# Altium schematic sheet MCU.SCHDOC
size B; Organization: Altium Limited; Address1: L3, 12a Rodborough Rd; Address2: Frenchs Forest; Address3: NSW; Address4: Australia 2086; DocumentNumber: 1; SheetNumber: 1; SheetTotal: 1
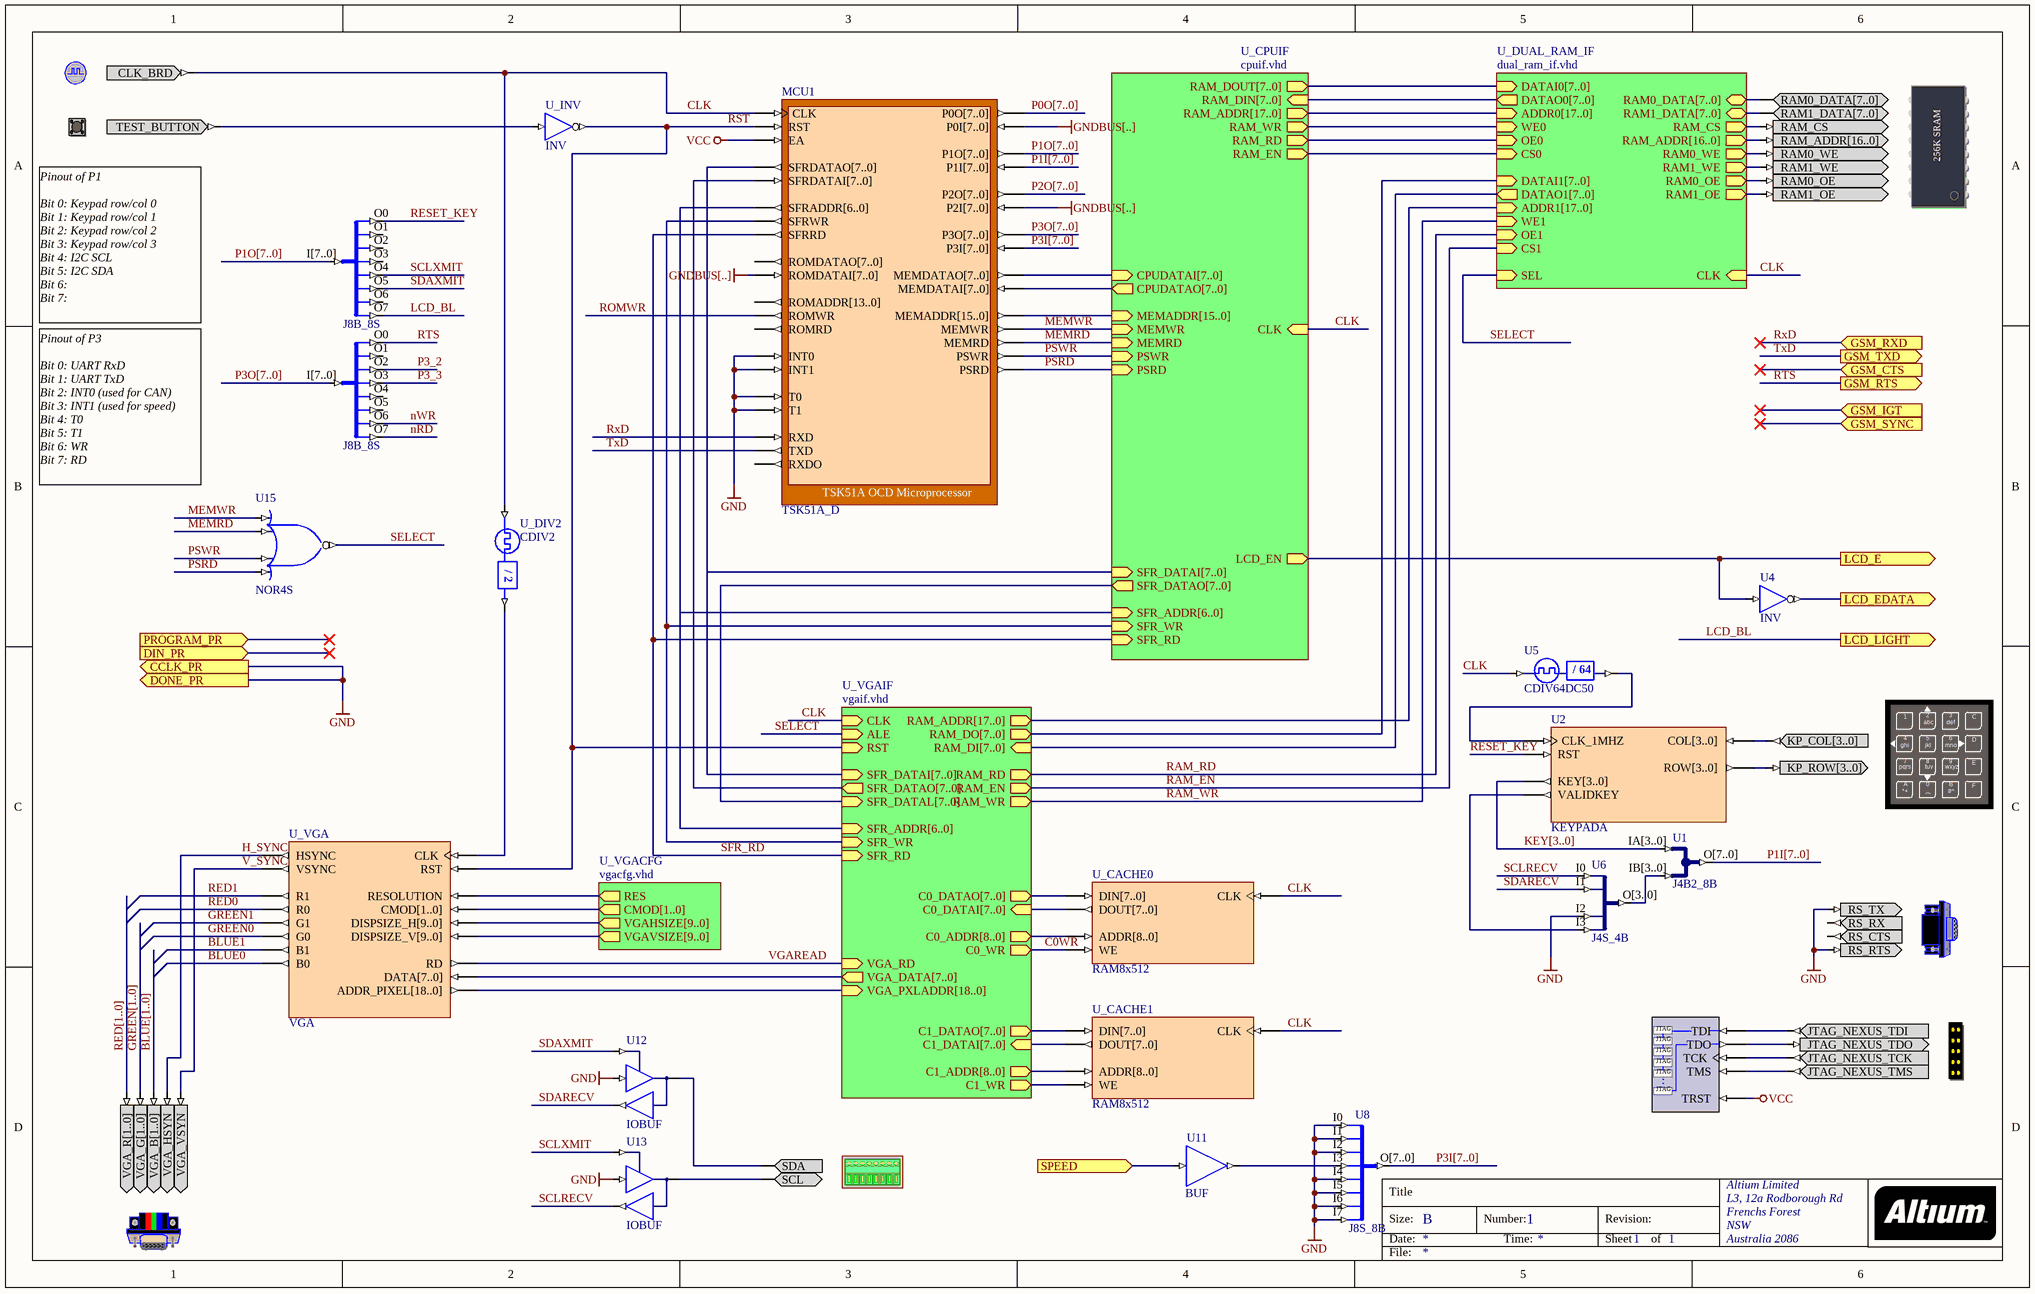
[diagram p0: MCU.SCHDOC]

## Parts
(Parts that share a designator on the sheet are numbered #1, #2 ... from top to bottom, then left to right.)
?#1  KEYPAD  (value not drawn)
?#2  RS232CNTR  (value not drawn)
?#3  NEXUS_JTAG_CONNECTOR  (value not drawn)
?#4  ADCDAC_I2C  (value not drawn)
MCU1  TSK51A_D
NEXUS_JTAG_PORT  NEXUS_JTAG_PORT  (value not drawn)
SRAM256kx8B  MEMORY256KX8  (value not drawn)
U1  J4B2_8B
U2  KEYPADA
U4  INV
U5  CDIV64DC50
U6  J4S_4B
U7  J8B_8S
U8  J8S_8B
U11  BUF
U12  IOBUF
U13  IOBUF
U15  NOR4S
U18  J8B_8S
U_CACHE0  RAM8x512
U_CACHE1  RAM8x512
U_CLKEXT  CLOCK_BOARD  (value not drawn)
U_DIV2  CDIV2
U_INV  INV
U_RSTEXT  TEST_BUTTON  (value not drawn)
U_VGA  VGA
U_VGAEXT  VGACNTR  (value not drawn)

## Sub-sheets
U_CPUIF = cpuif.vhd: MEMWR (in), RAM_EN (out), RAM_WR (out), RAM_RD (out), RAM_DOUT[7..0] (out), MEMRD (in), LCD_EN (out), RAM_ADDR[17..0] (out), CLK (in), SFR_ADDR[6..0] (in), SFR_DATAI[7..0] (in), SFR_DATAO[7..0] (out), SFR_WR (in), SFR_RD (in), RAM_DIN[7..0] (in), PSWR (in), PSRD (in), MEMADDR[15..0] (in), CPUDATAI[7..0] (in), CPUDATAO[7..0] (out)
U_DUAL_RAM_IF = dual_ram_if.vhd: DATAI0[7..0] (in), DATAI1[7..0] (in), DATAO0[7..0] (out), DATAO1[7..0] (out), ADDR0[17..0] (in), ADDR1[17..0] (in), WE0 (in), WE1 (in), OE0 (in), OE1 (in), CS0 (in), CS1 (in), SEL (in), RAM0_DATA[7..0] (bidir), RAM1_DATA[7..0] (bidir), RAM_ADDR[16..0] (out), RAM0_WE (out), RAM1_WE (out), RAM0_OE (out), RAM1_OE (out), RAM_CS (out), CLK (in)
U_VGACFG = vgacfg.vhd: RES (out), CMOD[1..0] (out), VGAHSIZE[9..0] (out), VGAVSIZE[9..0] (out)
U_VGAIF = vgaif.vhd: VGA_PXLADDR[18..0] (in), VGA_DATA[7..0] (out), VGA_RD (in), C1_WR (out), C1_ADDR[8..0] (out), C1_DATAI[7..0] (in), C1_DATAO[7..0] (out), C0_WR (out), C0_ADDR[8..0] (out), C0_DATAI[7..0] (in), C0_DATAO[7..0] (out), RAM_ADDR[17..0] (out), CLK (in), ALE (in), RAM_DO[7..0] (out), RAM_RD (out), RAM_EN (out), RAM_WR (out), SFR_ADDR[6..0] (in), SFR_DATAI[7..0] (in), SFR_DATAO[7..0] (out), SFR_WR (in), SFR_RD (in), SFR_DATAL[7..0] (in), RAM_DI[7..0] (in), RST (in)

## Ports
CCLK_PR (out), DIN_PR (in), DONE_PR (out), GSM_CTS (in), GSM_IGT (in), GSM_RTS (out), GSM_RXD (in), GSM_SYNC (in), GSM_TXD (out), LCD_E (out), LCD_EDATA (out), LCD_LIGHT (out), PROGRAM_PR (in), SPEED (in)

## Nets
GND: ?#2.RS_RTS ?#2.RS_TX MCU1.INT0 MCU1.INT1 MCU1.T0 MCU1.T1 U6.I2 U8.I0 U8.I1 U8.I2 U8.I4 U8.I5 U8.I6 U8.I7 U12.I U13.I ; port CCLK_PR, port DONE_PR
VCC: MCU1.EA NEXUS_JTAG_PORT.TRST
BLUE0: U_VGA.B0
BLUE1: U_VGA.B1
C0WR: U_CACHE0.WE ; sheet U_VGAIF/C0_WR
CLK: MCU1.CLK U5.CLKIN U_CACHE0.CLK U_CACHE1.CLK U_CLKEXT.CLK_BRD U_DIV2.CLKIN ; sheet U_CPUIF/CLK, sheet U_VGAIF/CLK, sheet U_DUAL_RAM_IF/CLK
GREEN0: U_VGA.G0
GREEN1: U_VGA.G1
H_SYNC: U_VGA.HSYNC U_VGAEXT.VGA_HSYN
LCD_BL: U18.O7 ; port LCD_LIGHT
LCD_E: U4.I ; port LCD_E, sheet U_CPUIF/LCD_EN
LCD_EDATA: U4.O ; port LCD_EDATA
MEMRD: MCU1.MEMRD U15.I1 ; sheet U_CPUIF/MEMRD
MEMWR: MCU1.MEMWR U15.I0 ; sheet U_CPUIF/MEMWR
nRD: U7.O7
nWR: U7.O6
P3_2: U7.O2
P3_3: U7.O3
PSRD: MCU1.PSRD U15.I3 ; sheet U_CPUIF/PSRD
PSWR: MCU1.PSWR U15.I2 ; sheet U_CPUIF/PSWR
RAM_EN: sheet U_VGAIF/RAM_EN, sheet U_DUAL_RAM_IF/CS1
RAM_RD: sheet U_VGAIF/RAM_RD, sheet U_DUAL_RAM_IF/OE1
RAM_WR: sheet U_VGAIF/RAM_WR, sheet U_DUAL_RAM_IF/WE1
RED0: U_VGA.R0
RED1: U_VGA.R1
RESET_KEY: U2.RST U18.O0
ROMWR: MCU1.ROMWR
RST: MCU1.RST U_INV.O U_VGA.RST ; sheet U_VGAIF/RST
RTS: U7.O0 ; port GSM_RTS
RxD: MCU1.RXD ; port GSM_RXD
SCLRECV: U6.I0 U13.O
SCLXMIT: U13.T U18.O4
SDARECV: U6.I1 U12.O
SDAXMIT: U12.T U18.O5
SELECT: U15.O ; sheet U_VGAIF/ALE, sheet U_DUAL_RAM_IF/SEL
SFR_RD: MCU1.SFRRD ; sheet U_CPUIF/SFR_RD, sheet U_VGAIF/SFR_RD
SPEED: U11.I ; port SPEED
TxD: MCU1.TXD ; port GSM_TXD
V_SYNC: U_VGA.VSYNC U_VGAEXT.VGA_VSYN
VGAREAD: U_VGA.RD ; sheet U_VGAIF/VGA_RD
Net?#3_JTAG_NEXUS_TCK: ?#3.JTAG_NEXUS_TCK NEXUS_JTAG_PORT.TCK
Net?#3_JTAG_NEXUS_TDI: ?#3.JTAG_NEXUS_TDI NEXUS_JTAG_PORT.TDI
Net?#3_JTAG_NEXUS_TDO: ?#3.JTAG_NEXUS_TDO NEXUS_JTAG_PORT.TDO
Net?#3_JTAG_NEXUS_TMS: ?#3.JTAG_NEXUS_TMS NEXUS_JTAG_PORT.TMS
Net?#4_SCL: ?#4.SCL U13.IO
Net?#4_SDA: ?#4.SDA U12.IO
NetMCU1_SFRWR: MCU1.SFRWR ; sheet U_CPUIF/SFR_WR, sheet U_VGAIF/SFR_WR
NetSRAM256kx8B_RAM0_OE: SRAM256kx8B.RAM0_OE ; sheet U_DUAL_RAM_IF/RAM0_OE
NetSRAM256kx8B_RAM0_WE: SRAM256kx8B.RAM0_WE ; sheet U_DUAL_RAM_IF/RAM0_WE
NetSRAM256kx8B_RAM1_OE: SRAM256kx8B.RAM1_OE ; sheet U_DUAL_RAM_IF/RAM1_OE
NetSRAM256kx8B_RAM1_WE: SRAM256kx8B.RAM1_WE ; sheet U_DUAL_RAM_IF/RAM1_WE
NetSRAM256kx8B_RAM_CS: SRAM256kx8B.RAM_CS ; sheet U_DUAL_RAM_IF/RAM_CS
NetU2_CLK_1MHZ: U2.CLK_1MHZ U5.CLKDV
NetU2_VALIDKEY: U2.VALIDKEY U6.I3
NetU8_I3: U8.I3 U11.O
NetU_CACHE1_WE: U_CACHE1.WE ; sheet U_VGAIF/C1_WR
NetU_DIV2_CLKDV: U_DIV2.CLKDV U_VGA.CLK
NetU_INV_I: U_INV.I U_RSTEXT.TEST_BUTTON
NetU_VGA_RESOLUTION: U_VGA.RESOLUTION ; sheet U_VGACFG/RES
(unnamed): sheet U_CPUIF/RAM_EN, sheet U_DUAL_RAM_IF/CS0
(unnamed): sheet U_CPUIF/RAM_WR, sheet U_DUAL_RAM_IF/WE0  [a separate net that carries the same name]
(unnamed): sheet U_CPUIF/RAM_RD, sheet U_DUAL_RAM_IF/OE0  [a separate net that carries the same name]

Not connected (* = marked no-connect by the designer): ?#1 KP_COL[3..0] KP_ROW[3..0]; ?#2 RS_CTS RS_RX; MCU1 MEMADDR[15..0] MEMDATAI[7..0] MEMDATAO[7..0] P0I[7..0] P0O[7..0] P1I[7..0] P1O[7..0] P2I[7..0] P2O[7..0] P3I[7..0] P3O[7..0] ROMADDR[13..0] ROMDATAI[7..0] ROMDATAO[7..0] ROMRD RXDO SFRADDR[6..0] SFRDATAI[7..0] SFRDATAO[7..0]; SRAM256kx8B RAM0_DATA[7..0] RAM1_DATA[7..0] RAM_ADDR[16..0]; U1 IA[3..0] IB[3..0] O[7..0]; U2 COL[3..0] KEY[3..0] ROW[3..0]; U6 O[3..0]; U7 I[7..0] O1 O4 O5; U8 O[7..0]; U18 I[7..0] O1 O2 O3 O6; U_CACHE0 ADDR[8..0] DIN[7..0] DOUT[7..0]; U_CACHE1 ADDR[8..0] DIN[7..0] DOUT[7..0]; U_VGA ADDR_PIXEL[18..0] CMOD[1..0] DATA[7..0] DISPSIZE_H[9..0] DISPSIZE_V[9..0]; U_VGAEXT VGA_B[1..0] VGA_G[1..0] VGA_R[1..0]

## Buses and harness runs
bus BLUE[1..0]
bus GREEN[1..0]
bus KEY[3..0]
bus P0O[7..0]
bus P1I[7..0]
bus P1O[7..0]
bus P2O[7..0]
bus P3I[7..0]
bus P3O[7..0]
bus RED[1..0]
bus sheet U_CPUIF/RAM_ADDR[17..0] = sheet U_DUAL_RAM_IF/ADDR0[17..0]
bus sheet U_CPUIF/RAM_DIN[7..0] = sheet U_DUAL_RAM_IF/DATAO0[7..0]
bus sheet U_CPUIF/RAM_DOUT[7..0] = sheet U_DUAL_RAM_IF/DATAI0[7..0]
bus sheet U_CPUIF/SFR_ADDR[6..0] = sheet U_VGAIF/SFR_ADDR[6..0]
bus sheet U_CPUIF/SFR_DATAI[7..0] = sheet U_VGAIF/SFR_DATAI[7..0]
bus sheet U_CPUIF/SFR_DATAO[7..0] = sheet U_VGAIF/SFR_DATAL[7..0]
bus sheet U_DUAL_RAM_IF/ADDR1[17..0] = sheet U_VGAIF/RAM_ADDR[17..0]
bus sheet U_DUAL_RAM_IF/DATAI1[7..0] = sheet U_VGAIF/RAM_DO[7..0]
bus sheet U_DUAL_RAM_IF/DATAO1[7..0] = sheet U_VGAIF/RAM_DI[7..0]

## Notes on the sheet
- (near U_RSTEXT) Pinout of P1
  Bit 0: Keypad row/col 0
  Bit 1: Keypad row/col 1
  Bit 2: Keypad row/col 2
  Bit 3: Keypad row/col 3
  Bit 4: I2C SCL
  Bit 5: I2C SDA
  Bit 6:
  Bit 7:
- Pinout of P3
  Bit 0: UART RxD
  Bit 1: UART TxD
  Bit 2: INT0 (used for CAN)
  Bit 3: INT1 (used for speed)
  Bit 4: T0
  Bit 5: T1
  Bit 6: WR
  Bit 7: RD
- Labels drawn without touching a wire or pin: GNDBUS[..]

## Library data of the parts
?#1 = KEYPAD: Key Pad; PortComponent: True
?#2 = RS232CNTR: DCE Serial Port Connector; PortComponent: True
?#3 = NEXUS_JTAG_CONNECTOR: JTAG Port; PortComponent: True
?#4 = ADCDAC_I2C: Analog Digital/ Digital Analog Converter, I2C Interface; PortComponent: True
MCU1 = TSK51A_D: TSK51A OCD Microprocessor; NEXUS_CORE: Processor_OCDS; NEXUS_JTAG_DEVICE: True; NEXUS_JTAG_ORDER: 0; ChildModel1: RAM256x8_TSK51D
NEXUS_JTAG_PORT = NEXUS_JTAG_PORT: Nexus Processor JTAG Chain Connector; NEXUS_JTAG_CONNECTOR: True
SRAM256kx8B = MEMORY256KX8: SRAM 256kx8; PortComponent: True
U1 = J4B2_8B: 2 x 4-Bit input bus to 1 x 8-bit output bus; Class I: Bus Joiner; ArchiveName: GENERIC
U2 = KEYPADA: Keypad
U4 U_INV = INV: Inverter; Class I: Logic Primitive; ArchiveName: GENERIC
U5 = CDIV64DC50: Clock Divider by 64 with 50% Duty Cycle Output; ArchiveName: GENERIC
U6 = J4S_4B: 4 Single pin inputs to single 4-Bit output bus; Class I: Bus Joiner; ArchiveName: GENERIC
U7 U18 = J8B_8S: 8-Bit input bus to 8 single pin outputs; Class I: Bus Joiner; ArchiveName: GENERIC
U8 = J8S_8B: 8 Single pin inputs to single 8-Bit output bus; Class I: Bus Joiner; ArchiveName: GENERIC
U11 = BUF: Buffer; ArchiveName: GENERIC
U12 U13 = IOBUF: Input/Output Buffer; ArchiveName: GENERIC
U15 = NOR4S: 4-Input NOR Gate, Single Pin Version; Xilinx Equivalent: NOR4; ArchiveName: GENERIC
U_CACHE0 U_CACHE1 = RAM8x512: Single Port Random Access Memory 512 x 8; Memory_Depth: 512; Memory_Type: RAM_SinglePortBlock; Memory_Width: 8; Memory_ClockEdge: Rising; Nexus_Core: Memory_Program
U_CLKEXT = CLOCK_BOARD: Global System Clock Suply; PortComponent: True
U_DIV2 = CDIV2: Clock Divider by 2; ArchiveName: GENERIC
U_RSTEXT = TEST_BUTTON: Test Button; PortComponent: True
U_VGA = VGA: VGA Controller
U_VGAEXT = VGACNTR: VGA Dsub-15-Female-HD; PortComponent: True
